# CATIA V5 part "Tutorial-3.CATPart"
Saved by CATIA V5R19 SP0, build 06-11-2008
Part number: Part1
Bounding box of the stored display mesh (mm): x -75 to 75, y -150 to 150, z 30 to 180
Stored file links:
  D:\Shriniwas\v5_r19\Part files\c05\c05tut3.CATPart
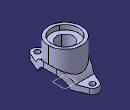
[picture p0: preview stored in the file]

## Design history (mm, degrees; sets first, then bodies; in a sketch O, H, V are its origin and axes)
Body1 (main body)
  Sketch1 on yz-plane, origin (0, 0, 0), H (0, 1, 0), V (0, 0, 1)
    point P1 (0, 42.5)
    line L1 (150, 55) -> (150, 30)
    line L2 (150, 30) -> (74.162, 30)
    line L3 (-150, 30) -> (-150, 55)
    line L4 (-150, 55) -> (-89.4427, 55)
    point P3 (150, 30)
    point P4 (-150, 30)
    arc A1 centre (0, 0) radius 80 from (74.162, 30) to (-74.162, 30) ccw
    point P7 (-74.162, 30)
    point P8 (0, 30)
    arc A2 centre (0, 0) radius 105 from (89.4427, 55) to (-89.4427, 55) ccw
    point P9 (89.4427, 55)
    line L5 (-74.162, 30) -> (-150, 30)
    line L6 (89.4427, 55) -> (150, 55)
    length L1 = 25
    distance H L2 = 30
    radius A1 = 80
    distance L3 L1 = 300
    radius A2 = 105
    coincidence: P1 V, P7 L2, P9 L4, L2 P8, L2 L5
    vertical: L1 V, L3 V
    horizontal: L2 H, L4 H, L5 H, L6 H
    equidistance: L1 L3 P1, L2 L4 P1, P3 P4 P8
  Pad1: profile Sketch1, direction (1, 0, 0), length 75, mirrored extent
  Sketch2 on xy-plane, origin (0, 0, 0), H (1, 0, 0), V (0, 1, 0)
    arc A1 centre (0, 0) radius 75 from (-68.7386, 30) to (-68.7386, -30) ccw
    point P1 (75, 0)
    arc A2 centre (0, 125) radius 25 from (22.9129, 135) to (-22.9129, 135) ccw
    point P2 (0, 125)
    point P3 (0, 150)
    arc A3 centre (0, -125) radius 25 from (-22.9129, -135) to (22.9129, -135) ccw
    point P4 (0, -125)
    point P5 (0, -150)
    reference projected line E1 (75, 89.4427) -> (75, -89.4427) from edge [face of Pad1 from Sketch1.A2 | end face of Pad1]
    reference projected line E2 (-75, 150) -> (75, 150) from edge [face of Pad1 from Sketch1.L6 | face of Pad1 from Sketch1.L1]
    reference projected line E3 (-75, -150) -> (75, -150) from edge [face of Pad1 from Sketch1.L3 | face of Pad1 from Sketch1.L4]
    line L1 (-22.9129, 135) -> (-68.7386, 30)
    line L2 (22.9129, 135) -> (68.7386, 30)
    line L3 (-68.7386, -30) -> (-22.9129, -135)
    line L4 (68.7386, -30) -> (22.9129, -135)
    point P12 (68.7386, -30)
    arc A4 centre (0, 0) radius 75 from (68.7386, -30) to (68.7386, 30) ccw
    radius A2 = 25
    radius A3 = 25
    coincidence: A1 P1, P1 H, P2 V, A2 P3, P3 V, P4 V, A3 P5, P5 V, A1 P12, A1 A4
    tangency: E1 A1, A2 E2, A3 E3, L1 A2, L1 A1, L2 A2, L2 A1, L3 A1, L3 A3, L4 A1, L4 A3
  Pocket1: profile Sketch2, direction (0, 0, 1), through (limit type 3), outer side
  Plane1: type Offset, Offset 180, RefPlane xy-plane
  Sketch3 on Plane1, origin (0, 0, 180), H (1, 0, 0), V (0, 1, 0)
    circle A1 centre (0, 0) radius 75
    radius A1 = 75
  Pad2: profile Sketch3, direction (0, 0, -1), up to face of Pad1 from Sketch1.A2
  Sketch4 on yz-plane, origin (0, 0, 0), H (0, 1, 0), V (0, 0, 1)
    line L1 (0, 0) -> (0, 180)
    line L2 (0, 180) -> (61.5, 180)
    line L3 (61.5, 180) -> (61.5, 160)
    line L4 (61.5, 160) -> (37.5, 160)
    line L5 (37.5, 160) -> (37.5, 0)
    point P5 (37.5, 0)
    line L6 (37.5, 0) -> (0, 0)
    reference projected line E1 (-75, 180) -> (75, 180) from edge [face of Pad2 from Sketch3.A1 | start face of Pad2]
    axis line L7 (0, 214.9745) -> (0, -17.6606)
    point P6 (0, 214.9745)
    length L3 = 20
    "Radius" L7 L5 = 37.5
    "Radius" L7 L3 = 61.5
    vertical: L1 V, L3 V, L5 V, L7 V
    horizontal: L2 H, L4 H, L6 H
    coincidence: P5 H, L2 E1, P6 V
  Groove1: profile Sketch4, axis Sketch4.L7, angle 360
  Sketch5 on face of Pad1 from Sketch1.L6, origin (0, 0, 55), H (1, 0, 0), V (0, 1, 0)
    circle A1 centre (0, 125) radius 12.5
    point P1 (0, 125)
    reference projected arc E1 centre (0, 125) radius 25 from (22.9129, 135) to (-22.9129, 135) ccw from edge [face of Pad1 from Sketch1.L6 | face of Pocket1]
    circle A2 centre (0, -125) radius 12.5
    radius A1 = 12.5
    concentricity: P1 E1
    symmetry: A1 A2 H
  Pocket2: profile Sketch5, direction (0, 0, -1), through (limit type 3)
